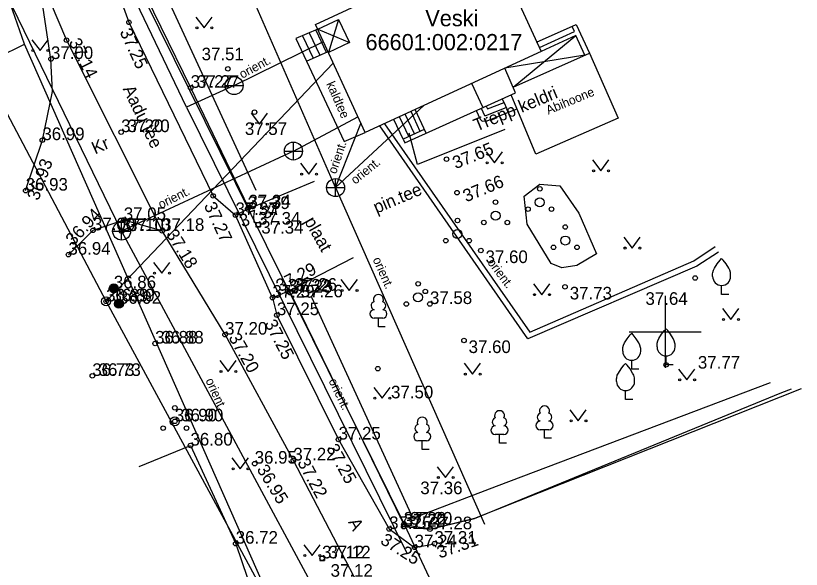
# Model space of a CAD drawing. Extents: x 627548 to 628052, y 6467984 to 6468802.
# Drawn here: x 627663.96 to 627707.55, y 6468336.82 to 6468367.55 of the extents above; entities that cross this region are included whole.
import ezdxf

# ---------------------------------------------------------------- set-up
doc = ezdxf.new("R2010")
doc.units = 0
for name, color, linetype in [('ABIJOONIS', 7, 'Continuous'), ('AED', 7, 'Continuous'), ('HALJASTUS', 7, 'Continuous'), ('HOONE', 7, 'Continuous'), ('HOONEDET', 7, 'Continuous'), ('KKAEV', 7, 'Continuous'), ('KORGUS-EH2000', 7, 'Continuous'), ('KTRASS', 7, 'Continuous'), ('MOOTKORG-EH2000', 7, 'Continuous'), ('MOOTMPUNKT', 7, 'Continuous'), ('MPOHULIIN', 7, 'Continuous'), ('PIIR', 7, 'Continuous'), ('POST', 7, 'Continuous'), ('PUU', 7, 'Continuous'), ('RAJATIS', 7, 'Continuous'), ('SIOHULIIN', 7, 'Continuous'), ('SKKAEV', 7, 'Continuous'), ('SKTRASS', 7, 'Continuous'), ('TEE', 7, 'Continuous'), ('TTRASS', 7, 'Continuous'), ('VKAEV', 7, 'Continuous'), ('VORK', 7, 'Continuous'), ('VTRASS', 7, 'Continuous')]:
    doc.layers.add(name, color=color, linetype=linetype)

msp = doc.modelspace()

# ---------------------------------------------------------------- linework, layer by layer
at = {"layer": 'ABIJOONIS'}
msp.add_lwpolyline([(627691.095, 6468361.243), (627686.259, 6468359.289), (627685.788, 6468361.021)], dxfattribs=at)
at = {"layer": 'AED'}
for p, q in [((627677.288, 6468356.078), (627677.288, 6468355.828)), ((627677.288, 6468356.078), (627677.538, 6468356.078)), ((627677.538, 6468356.078), (627677.538, 6468355.828)), ((627677.288, 6468355.828), (627677.538, 6468355.828)), ((627679.187, 6468352.178), (627685.495, 6468339.298)), ((627679.318, 6468352.408), (627679.318, 6468352.158)), ((627679.318, 6468352.408), (627679.568, 6468352.408)), ((627679.318, 6468352.158), (627679.568, 6468352.158)), ((627679.568, 6468352.408), (627679.568, 6468352.158)), ((627680.837, 6468337.547), (627680.837, 6468337.297)), ((627680.837, 6468337.547), (627681.087, 6468337.547)), ((627680.837, 6468337.297), (627681.087, 6468337.297)), ((627681.087, 6468337.547), (627681.087, 6468337.297))]:
    msp.add_line(p, q, dxfattribs=at)
for points in [[(627676.876, 6468356.909), (627673.668, 6468363.549), (627670.384, 6468370.298)], [(627685.489, 6468339.183), (627686.945, 6468339.039), (627689.41, 6468339.63), (627706.473, 6468346.623), (627707.003, 6468346.838)], [(627670.805, 6468342.532), (627673.658, 6468343.687), (627676.168, 6468338.238), (627677.141, 6468335.391)]]:
    msp.add_lwpolyline(points, dxfattribs=at)
at = {"layer": 'HALJASTUS'}
for p, q in [((627673.956, 6468367.48), (627674.419, 6468366.873)), ((627674.419, 6468366.873), (627674.865, 6468367.48)), ((627664.852, 6468366.221), (627665.316, 6468365.614)), ((627665.316, 6468365.614), (627665.761, 6468366.221)), ((627677.031, 6468362.139), (627677.495, 6468361.532)), ((627677.495, 6468361.532), (627677.94, 6468362.139)), ((627690.061, 6468359.994), (627690.525, 6468359.387)), ((627690.525, 6468359.387), (627690.97, 6468359.994)), ((627695.969, 6468359.549), (627696.432, 6468358.942)), ((627696.432, 6468358.942), (627696.878, 6468359.549)), ((627679.764, 6468359.357), (627680.228, 6468358.75)), ((627680.228, 6468358.75), (627680.673, 6468359.357)), ((627697.709, 6468355.259), (627698.172, 6468354.653)), ((627698.172, 6468354.653), (627698.618, 6468355.259)), ((627671.6, 6468353.857), (627672.064, 6468353.25)), ((627672.064, 6468353.25), (627672.509, 6468353.857)), ((627682.008, 6468352.906), (627682.471, 6468352.299)), ((627682.471, 6468352.299), (627682.917, 6468352.906)), ((627692.691, 6468352.67), (627693.155, 6468352.063)), ((627693.155, 6468352.063), (627693.6, 6468352.67)), ((627703.172, 6468351.294), (627703.635, 6468350.687)), ((627703.635, 6468350.687), (627704.081, 6468351.294)), ((627675.288, 6468348.409), (627675.752, 6468347.802)), ((627675.752, 6468347.802), (627676.197, 6468348.409)), ((627688.847, 6468348.259), (627689.311, 6468347.652)), ((627689.311, 6468347.652), (627689.756, 6468348.259)), ((627700.744, 6468347.935), (627701.207, 6468347.329)), ((627701.207, 6468347.329), (627701.653, 6468347.935)), ((627683.829, 6468346.917), (627684.292, 6468346.31)), ((627684.292, 6468346.31), (627684.738, 6468346.917)), ((627694.715, 6468345.669), (627695.178, 6468345.062)), ((627695.178, 6468345.062), (627695.624, 6468345.669)), ((627675.959, 6468343.002), (627676.422, 6468342.395)), ((627676.422, 6468342.395), (627676.868, 6468343.002)), ((627687.35, 6468342.513), (627687.813, 6468341.906)), ((627687.813, 6468341.906), (627688.259, 6468342.513)), ((627679.941, 6468338.182), (627680.404, 6468337.575)), ((627680.404, 6468337.575), (627680.85, 6468338.182))]:
    msp.add_line(p, q, dxfattribs=at)
for points in [[(627677.3, 6468357.854), (627671.313, 6468370.862)], [(627680.378, 6468351.925), (627685.999, 6468339.649), (627690.64, 6468341.424), (627705.838, 6468347.182)]]:
    msp.add_lwpolyline(points, dxfattribs=at)
msp.add_lwpolyline([(627692.168, 6468357.525), (627693.041, 6468358.202), (627694.161, 6468358.107), (627695.212, 6468356.587), (627696.187, 6468354.33), (627695.094, 6468353.691), (627694.27, 6468353.556), (627693.664, 6468353.792), (627692.336, 6468355.978)], close=True, dxfattribs=at)
for centre, radius in [((627674.018, 6468366.873), 0.055), ((627674.847, 6468366.873), 0.055), ((627664.915, 6468365.614), 0.055), ((627665.744, 6468365.614), 0.055), ((627677.094, 6468361.532), 0.055), ((627677.922, 6468361.532), 0.055), ((627690.123, 6468359.387), 0.055), ((627690.952, 6468359.387), 0.055), ((627696.031, 6468358.942), 0.055), ((627696.86, 6468358.942), 0.055), ((627679.827, 6468358.75), 0.055), ((627680.656, 6468358.75), 0.055), ((627693.042, 6468357.939), 0.125), ((627690.587, 6468357.199), 0.125), ((627693.042, 6468357.189), 0.25), ((627692.392, 6468356.814), 0.125), ((627693.692, 6468356.814), 0.125), ((627690.587, 6468356.449), 0.25), ((627688.474, 6468356.183), 0.125), ((627689.937, 6468356.074), 0.125), ((627691.237, 6468356.074), 0.125), ((627694.455, 6468355.82), 0.125), ((627688.474, 6468355.433), 0.25), ((627687.824, 6468355.058), 0.125), ((627689.124, 6468355.058), 0.125), ((627694.455, 6468355.07), 0.25), ((627693.805, 6468354.695), 0.125), ((627695.105, 6468354.695), 0.125), ((627697.771, 6468354.653), 0.055), ((627698.6, 6468354.653), 0.055), ((627671.663, 6468353.25), 0.055), ((627672.491, 6468353.25), 0.055), ((627686.288, 6468352.668), 0.125), ((627682.07, 6468352.299), 0.055), ((627682.899, 6468352.299), 0.055), ((627686.288, 6468351.918), 0.25), ((627692.754, 6468352.063), 0.055), ((627693.583, 6468352.063), 0.055), ((627685.638, 6468351.543), 0.125), ((627686.938, 6468351.543), 0.125), ((627703.234, 6468350.687), 0.055), ((627704.063, 6468350.687), 0.055), ((627675.351, 6468347.802), 0.055), ((627676.18, 6468347.802), 0.055), ((627688.91, 6468347.652), 0.055), ((627689.738, 6468347.652), 0.055), ((627700.806, 6468347.329), 0.055), ((627701.635, 6468347.329), 0.055), ((627683.891, 6468346.31), 0.055), ((627684.72, 6468346.31), 0.055), ((627694.777, 6468345.062), 0.055), ((627695.606, 6468345.062), 0.055), ((627676.021, 6468342.395), 0.055), ((627676.85, 6468342.395), 0.055), ((627687.412, 6468341.906), 0.055), ((627688.241, 6468341.906), 0.055), ((627680.003, 6468337.575), 0.055), ((627680.832, 6468337.575), 0.055)]:
    msp.add_circle(centre, radius, dxfattribs=at)
at = {"layer": 'HOONE'}
for points in [[(627683.344, 6468361.058), (627680.604, 6468367.07), (627683.347, 6468368.337), (627681.543, 6468372.245), (627686.517, 6468374.421), (627686.768, 6468373.881), (627688.585, 6468374.705), (627688.345, 6468375.224), (627688.627, 6468375.344), (627693.124, 6468365.572), (627683.344, 6468361.058)], [(627680.724, 6468366.805), (627681.873, 6468367.335), (627682.475, 6468366.069), (627681.312, 6468365.516)], [(627695.541, 6468365.357), (627695.045, 6468366.447), (627693.124, 6468365.572)], [(627691.564, 6468363.583), (627695.794, 6468365.47), (627697.389, 6468361.86), (627692.828, 6468359.858), (627691.451, 6468363.164)]]:
    msp.add_lwpolyline(points, dxfattribs=at)
at = {"layer": 'HOONEDET'}
for points in [[(627681.873, 6468367.335), (627681.312, 6468365.516)], [(627692.858, 6468366.087), (627695.061, 6468367.064), (627695.794, 6468365.47)], [(627694.96, 6468366.668), (627694.83, 6468366.961)], [(627680.723, 6468366.809), (627679.504, 6468366.28), (627680.103, 6468365.025), (627681.289, 6468365.566)], [(627679.871, 6468366.439), (627680.467, 6468365.191)], [(627680.238, 6468366.599), (627680.831, 6468365.357)], [(627680.605, 6468366.758), (627681.195, 6468365.523)], [(627680.724, 6468366.805), (627682.475, 6468366.069)], [(627691.564, 6468363.583), (627695.045, 6468366.447)], [(627693.018, 6468365.793), (627694.96, 6468366.668)], [(627695.541, 6468365.357), (627691.094, 6468364.635)], [(627680.103, 6468365.025), (627682.185, 6468360.576), (627683.344, 6468361.058)], [(627686.633, 6468361.234), (627685.453, 6468360.695), (627685.546, 6468360.487), (627691.7, 6468363.277), (627691.094, 6468364.635)], [(627689.885, 6468362.466), (627689.272, 6468363.794)], [(627690.961, 6468362.942), (627691.305, 6468362.188)], [(627690.063, 6468362.535), (627690.135, 6468362.376), (627691.056, 6468362.735)], [(627686.09, 6468360.986), (627685.58, 6468362.09)], [(627686.408, 6468361.131), (627685.898, 6468362.237)], [(627686.731, 6468361.022), (627686.122, 6468362.34)], [(627689.517, 6468362.287), (627689.731, 6468361.814), (627689.837, 6468361.688), (627690.114, 6468361.724), (627691.305, 6468362.188)], [(627689.79, 6468362.411), (627689.972, 6468362.008), (627690.039, 6468362.017), (627691.181, 6468362.461)], [(627691.305, 6468362.188), (627691.78, 6468362.373)], [(627685.453, 6468360.695), (627684.944, 6468361.797)], [(627685.771, 6468360.84), (627685.262, 6468361.943)]]:
    msp.add_lwpolyline(points, dxfattribs=at)
at = {"layer": 'KKAEV'}
for p, q in [((627679.37, 6468359.539), (627679.37, 6468360.539)), ((627678.87, 6468360.039), (627679.87, 6468360.039)), ((627669.837, 6468355.094), (627669.837, 6468356.094)), ((627669.337, 6468355.594), (627670.337, 6468355.594))]:
    msp.add_line(p, q, dxfattribs=at)
for centre in [(627679.37, 6468360.039), (627669.837, 6468355.594)]:
    msp.add_circle(centre, 0.5, dxfattribs=at)
at = {"layer": 'KORGUS-EH2000'}
for centre in [(627670.241, 6468367.186), (627666.781, 6468366.19), (627675.734, 6468364.598), (627677.209, 6468362.197), (627687.869, 6468359.582), (627674.912, 6468357.546), (627688.444, 6468357.728), (627689.773, 6468354.518), (627701.666, 6468352.987), (627694.444, 6468352.498), (627686.687, 6468352.244), (627688.832, 6468349.522), (627684.055, 6468347.956), (627700.051, 6468348.164), (627685.999, 6468339.649)]:
    msp.add_circle(centre, 0.125, dxfattribs=at)
at = {"layer": 'KTRASS'}
for points in [[(627669.837, 6468355.594), (627653.907, 6468388.368), (627661.842, 6468392.243)], [(627679.37, 6468360.039), (627682.943, 6468361.938)], [(627679.37, 6468360.039), (627669.837, 6468355.594)], [(627669.837, 6468355.594), (627687.419, 6468322.91)]]:
    msp.add_lwpolyline(points, dxfattribs=at)
at = {"layer": 'MOOTMPUNKT'}
for centre in [(627665.915, 6468365.146), (627673.668, 6468363.549), (627669.809, 6468361.089), (627665.439, 6468360.645), (627664.511, 6468357.839), (627676.827, 6468356.817), (627676.876, 6468356.909), (627676.157, 6468356.482), (627669.957, 6468356.207), (627677.413, 6468355.953), (627668.244, 6468355.634), (627669.837, 6468355.594), (627672.084, 6468355.605), (627666.883, 6468354.283), (627669.403, 6468352.411), (627678.206, 6468351.895), (627679.054, 6468352.235), (627679.187, 6468352.178), (627679.443, 6468352.283), (627668.977, 6468351.69), (627669.684, 6468351.558), (627678.454, 6468350.927), (627675.577, 6468349.845), (627671.697, 6468349.35), (627668.209, 6468347.553), (627672.788, 6468345.029), (627673.658, 6468343.687), (627681.876, 6468344.022), (627679.367, 6468342.859), (627677.218, 6468342.682), (627685.495, 6468339.298), (627684.682, 6468339.053), (627685.489, 6468339.183), (627686.945, 6468339.039), (627676.168, 6468338.238), (627686.094, 6468338.034), (627687.197, 6468338.236), (627680.962, 6468337.422)]:
    msp.add_circle(centre, 0.125, dxfattribs=at)
at = {"layer": 'MPOHULIIN'}
for points in [[(627647.118, 6468393.14), (627668.977, 6468351.69)], [(627668.977, 6468351.69), (627681.581, 6468364.925)], [(627668.977, 6468351.69), (627685.459, 6468321.228)]]:
    msp.add_lwpolyline(points, dxfattribs=at)
at = {"layer": 'PIIR'}
for p, q in [((627664.45, 6468365.98), (627644.75, 6468421.52)), ((627685.55, 6468339.27), (627668.1, 6468374.6)), ((627653.556, 6468360.522), (627664.45, 6468365.98)), ((627693.67, 6468299.87), (627664.45, 6468365.98)), ((627707.553, 6468346.842), (627689.41, 6468339.63)), ((627689.41, 6468339.63), (627687.01, 6468339.05)), ((627702.17, 6468303.93), (627685.55, 6468339.27)), ((627687.01, 6468339.05), (627685.55, 6468339.27))]:
    msp.add_line(p, q, dxfattribs=at)
at = {"layer": 'POST'}
for radius in [0.25, 0.0234]:
    msp.add_circle((627668.977, 6468351.69), radius, dxfattribs=at)
at = {"layer": 'PUU'}
for p, q in [((627703.134, 6468352.074), (627703.134, 6468352.574)), ((627703.534, 6468352.074), (627703.134, 6468352.074)), ((627684.326, 6468350.754), (627683.846, 6468350.754)), ((627684.086, 6468350.279), (627684.086, 6468350.754)), ((627684.466, 6468350.279), (627684.086, 6468350.279)), ((627700.051, 6468348.164), (627700.051, 6468348.664)), ((627698.141, 6468347.92), (627698.141, 6468348.42)), ((627700.451, 6468348.164), (627700.051, 6468348.164)), ((627698.541, 6468347.92), (627698.141, 6468347.92)), ((627697.799, 6468346.24), (627697.799, 6468346.74)), ((627698.199, 6468346.24), (627697.799, 6468346.24)), ((627691.049, 6468344.3), (627690.569, 6468344.3)), ((627690.809, 6468343.825), (627690.809, 6468344.3)), ((627693.545, 6468344.563), (627693.065, 6468344.563)), ((627693.305, 6468344.088), (627693.305, 6468344.563)), ((627686.759, 6468343.943), (627686.279, 6468343.943)), ((627686.519, 6468343.468), (627686.519, 6468343.943)), ((627691.189, 6468343.825), (627690.809, 6468343.825)), ((627693.685, 6468344.088), (627693.305, 6468344.088)), ((627686.899, 6468343.468), (627686.519, 6468343.468))]:
    msp.add_line(p, q, dxfattribs=at)
for points in [[(627702.634, 6468353.074), (627702.634, 6468353.224), (627702.644, 6468353.289), (627702.679, 6468353.419), (627702.739, 6468353.539), (627702.884, 6468353.774), (627703.044, 6468353.979), (627703.134, 6468354.074)], [(627703.634, 6468353.074), (627703.634, 6468353.224), (627703.624, 6468353.289), (627703.589, 6468353.419), (627703.529, 6468353.539), (627703.384, 6468353.774), (627703.224, 6468353.979), (627703.134, 6468354.074)], [(627697.641, 6468348.92), (627697.641, 6468349.07), (627697.651, 6468349.135), (627697.686, 6468349.265), (627697.746, 6468349.385), (627697.891, 6468349.62), (627698.051, 6468349.825), (627698.141, 6468349.92)], [(627698.641, 6468348.92), (627698.641, 6468349.07), (627698.631, 6468349.135), (627698.596, 6468349.265), (627698.536, 6468349.385), (627698.391, 6468349.62), (627698.231, 6468349.825), (627698.141, 6468349.92)], [(627699.551, 6468349.164), (627699.551, 6468349.314), (627699.561, 6468349.379), (627699.596, 6468349.509), (627699.656, 6468349.629), (627699.801, 6468349.864), (627699.961, 6468350.069), (627700.051, 6468350.164)], [(627700.551, 6468349.164), (627700.551, 6468349.314), (627700.541, 6468349.379), (627700.506, 6468349.509), (627700.446, 6468349.629), (627700.301, 6468349.864), (627700.141, 6468350.069), (627700.051, 6468350.164)], [(627697.299, 6468347.24), (627697.299, 6468347.39), (627697.309, 6468347.455), (627697.344, 6468347.585), (627697.404, 6468347.705), (627697.549, 6468347.94), (627697.709, 6468348.145), (627697.799, 6468348.24)], [(627698.299, 6468347.24), (627698.299, 6468347.39), (627698.289, 6468347.455), (627698.254, 6468347.585), (627698.194, 6468347.705), (627698.049, 6468347.94), (627697.889, 6468348.145), (627697.799, 6468348.24)]]:
    msp.add_lwpolyline(points, dxfattribs=at)
for centre, radius in [((627672.788, 6468345.779), 0.125), ((627672.788, 6468345.029), 0.25), ((627672.138, 6468344.654), 0.125), ((627673.438, 6468344.654), 0.125)]:
    msp.add_circle(centre, radius, dxfattribs=at)
for centre, radius, start, end in [((627703.134, 6468353.074), 0.5, 180, 0), ((627684.086, 6468351.799), 0.277, 332.5799, 207.4201), ((627683.916, 6468351.452), 0.233, 109.0217, 253.1415), ((627684.256, 6468351.452), 0.233, 286.8508, 70.9859), ((627683.849, 6468350.991), 0.238, 90.0016, 269.3953), ((627684.323, 6468350.991), 0.238, 270.6047, 89.9984), ((627700.051, 6468349.164), 0.5, 180, 0), ((627698.141, 6468348.92), 0.5, 180, 0), ((627697.799, 6468347.24), 0.5, 180, 0), ((627690.809, 6468345.345), 0.277, 332.5799, 207.4201), ((627693.135, 6468345.261), 0.233, 109.0217, 253.1415), ((627693.305, 6468345.608), 0.277, 332.5799, 207.4201), ((627693.475, 6468345.261), 0.233, 286.8508, 70.9859), ((627686.519, 6468344.988), 0.277, 332.5799, 207.4201), ((627690.639, 6468344.998), 0.233, 109.0217, 253.1415), ((627690.979, 6468344.998), 0.233, 286.8508, 70.9859), ((627693.068, 6468344.8), 0.238, 90.0016, 269.3953), ((627693.542, 6468344.8), 0.238, 270.6047, 89.9984), ((627686.349, 6468344.641), 0.233, 109.0217, 253.1415), ((627686.689, 6468344.641), 0.233, 286.8508, 70.9859), ((627690.572, 6468344.537), 0.238, 90.0016, 269.3953), ((627691.046, 6468344.537), 0.238, 270.6047, 89.9984), ((627686.282, 6468344.18), 0.238, 90.0016, 269.3953), ((627686.756, 6468344.18), 0.238, 270.6047, 89.9984)]:
    msp.add_arc(centre, radius, start, end, dxfattribs=at)
at = {"layer": 'RAJATIS'}
for centre, radius in [((627669.403, 6468352.411), 0.25), ((627669.403, 6468352.411), 0.225), ((627669.403, 6468352.411), 0.2), ((627669.403, 6468352.411), 0.175), ((627669.403, 6468352.411), 0.15), ((627669.403, 6468352.411), 0.125), ((627669.403, 6468352.411), 0.1), ((627669.403, 6468352.411), 0.075), ((627669.403, 6468352.411), 0.05), ((627669.403, 6468352.411), 0.025), ((627669.684, 6468351.558), 0.25), ((627669.684, 6468351.558), 0.225), ((627669.684, 6468351.558), 0.2), ((627669.684, 6468351.558), 0.175), ((627669.684, 6468351.558), 0.15), ((627669.684, 6468351.558), 0.125), ((627669.684, 6468351.558), 0.1), ((627669.684, 6468351.558), 0.075), ((627669.684, 6468351.558), 0.05), ((627669.684, 6468351.558), 0.025)]:
    msp.add_circle(centre, radius, dxfattribs=at)
at = {"layer": 'SIOHULIIN'}
for points in [[(627647.118, 6468393.14), (627668.977, 6468351.69)], [(627668.977, 6468351.69), (627685.459, 6468321.228)]]:
    msp.add_lwpolyline(points, dxfattribs=at)
at = {"layer": 'SKKAEV'}
for p, q in [((627681.712, 6468357.505), (627681.712, 6468358.505)), ((627681.212, 6468358.005), (627682.212, 6468358.005))]:
    msp.add_line(p, q, dxfattribs=at)
msp.add_circle((627681.712, 6468358.005), 0.5, dxfattribs=at)
at = {"layer": 'SKTRASS'}
for points in [[(627681.712, 6468358.005), (627673.151, 6468377.568)], [(627681.712, 6468358.005), (627686.634, 6468362.576)], [(627681.712, 6468358.005), (627683.11, 6468361.572)], [(627681.712, 6468358.005), (627689.966, 6468339.313)]]:
    msp.add_lwpolyline(points, dxfattribs=at)
at = {"layer": 'TEE'}
for points in [[(627664.163, 6468372.339), (627666.781, 6468366.19), (627672.084, 6468355.605)], [(627669.275, 6468369.857), (627670.241, 6468367.186), (627674.912, 6468357.546), (627676.157, 6468356.482)], [(627664.511, 6468357.839), (627665.439, 6468360.645), (627665.995, 6468363.347), (627665.915, 6468365.146), (627665.379, 6468368.721)], [(627682.692, 6468354.105), (627679.054, 6468352.235), (627678.206, 6468351.895), (627676.157, 6468356.482), (627676.827, 6468356.817), (627680.541, 6468358.373)], [(627705.987, 6468287.879), (627701.575, 6468297.521), (627698.392, 6468302.759), (627693.344, 6468314.297), (627684.494, 6468333.036), (627679.367, 6468342.859), (627675.577, 6468349.845), (627672.084, 6468355.605), (627669.957, 6468356.207), (627668.244, 6468355.634), (627666.883, 6468354.283)], [(627678.206, 6468351.895), (627678.454, 6468350.927), (627681.876, 6468344.022), (627684.682, 6468339.053), (627686.094, 6468338.034), (627687.197, 6468338.236)]]:
    msp.add_lwpolyline(points, dxfattribs=at)
at = {"layer": 'TTRASS'}
for points in [[(627702.954, 6468354.418), (627701.766, 6468353.642), (627692.375, 6468349.612), (627684.159, 6468361.434)], [(627684.418, 6468361.554), (627692.482, 6468349.989)], [(627692.482, 6468349.989), (627701.598, 6468353.949), (627702.78, 6468354.733)]]:
    msp.add_lwpolyline(points, dxfattribs=at)
at = {"layer": 'VKAEV'}
msp.add_line((627675.581, 6468363.674), (627676.581, 6468363.674), dxfattribs=at)
msp.add_circle((627676.081, 6468363.674), 0.5, dxfattribs=at)
at = {"layer": 'VORK'}
for p, q in [((627700, 6468352), (627700, 6468348)), ((627698, 6468350), (627702, 6468350))]:
    msp.add_line(p, q, dxfattribs=at)
at = {"layer": 'VTRASS'}
for points in [[(627673.444, 6468362.479), (627667.441, 6468375)], [(627676.081, 6468363.674), (627681.04, 6468366.113)], [(627676.081, 6468363.674), (627673.444, 6468362.479), (627685.681, 6468337.682)]]:
    msp.add_lwpolyline(points, dxfattribs=at)

# ---------------------------------------------------------------- texts
at = {"layer": 'ABIJOONIS'}
msp.add_text('Trepp keldri', height=0.7, rotation=22.6199, dxfattribs=at).set_placement((627689.537, 6468361.112))
at = {"layer": 'HOONE'}
msp.add_text('Abihoone', height=0.5, rotation=22.6199, dxfattribs=at).set_placement((627693.513, 6468362.053))
at = {"layer": 'HOONEDET'}
msp.add_text('kaldtee', height=0.5, rotation=293.8929, dxfattribs=at).set_placement((627681.182, 6468363.77))
at = {"layer": 'KORGUS-EH2000'}
for s, rotation, p in [(' 37.25 ', 294.64, (627669.605, 6468366.894)), (' 37.14 ', 296.1947, (627666.774, 6468366.332)), (' 37.65 ', 21.8076, (627688.129, 6468358.932)), ('36.93', 69.7171, (627665.216, 6468357.25)), (' 37.66 ', 22.7762, (627688.715, 6468357.083)), ('37.37', 19.9771, (627676.529, 6468355.795)), ('36.94', 47.0081, (627667.162, 6468354.745)), (' 37.27 ', 294.8216, (627674.277, 6468357.252)), ('37.18', 301.6035, (627672.278, 6468355.43)), ('37.29', 27.2153, (627678.633, 6468352.195)), ('37.25', 297.2972, (627677.748, 6468350.469)), ('37.20', 299.5038, (627675.75, 6468349.686)), ('37.25', 298.5788, (627681.179, 6468343.549)), ('37.22', 298.289, (627679.568, 6468342.753)), ('36.95', 301.4002, (627677.31, 6468342.37)), ('37.25', 327.6206, (627684.141, 6468338.282)), ('37.31', 18.9768, (627687.478, 6468337.41))]:
    msp.add_text(s, height=0.7, rotation=rotation, dxfattribs=at).set_placement(p)
for s, p in [(' 37.51 ', (627674.014, 6468365.077)), ('37.27', (627674.018, 6468363.549)), ('37.20', (627670.159, 6468361.089)), (' 37.57 ', (627676.416, 6468360.929)), ('37.10', (627670.187, 6468355.594)), ('37.34', (627677.585, 6468355.453)), (' 37.60 ', (627689.773, 6468353.818)), ('37.26', (627679.771, 6468351.916)), (' 37.73 ', (627694.444, 6468351.798)), ('36.89', (627669.327, 6468351.69)), (' 37.58 ', (627686.687, 6468351.544)), (' 37.64 ', (627698.646, 6468351.498)), ('36.88', (627672.047, 6468349.35)), (' 37.60 ', (627688.832, 6468348.822)), (' 37.77 ', (627701.555, 6468347.957)), ('36.73', (627668.559, 6468347.553)), (' 37.50 ', (627684.527, 6468346.306)), ('36.90', (627673.138, 6468345.029)), (' 37.36 ', (627686.15, 6468340.986)), ('37.20', (627685.845, 6468339.298)), ('37.12', (627681.312, 6468337.422))]:
    msp.add_text(s, height=0.7, dxfattribs=at).set_placement(p)
at = {"layer": 'KTRASS'}
for rotation, p in [(26.6891, (627672.017, 6468356.82)), (294.3985, (627674.479, 6468347.302))]:
    msp.add_text('orient.', height=0.5, rotation=rotation, dxfattribs=at).set_placement(p)
at = {"layer": 'MOOTKORG-EH2000'}
for s, p in [('37.00', (627665.915, 6468365.146)), ('37.27', (627673.668, 6468363.549)), ('37.20', (627669.809, 6468361.089)), ('36.99', (627665.439, 6468360.645)), ('36.93', (627664.511, 6468357.839)), ('37.39', (627676.827, 6468356.817)), ('37.34', (627676.876, 6468356.909)), ('37.05', (627669.957, 6468356.207)), ('37.37', (627676.157, 6468356.482)), ('37.34', (627677.413, 6468355.953)), ('37.00', (627668.244, 6468355.634)), ('37.10', (627669.837, 6468355.594)), ('37.18', (627672.084, 6468355.605)), ('36.94', (627666.883, 6468354.283)), ('36.86', (627669.403, 6468352.411)), ('37.32', (627679.054, 6468352.235)), ('37.23', (627679.187, 6468352.178)), ('37.26', (627679.443, 6468352.283)), ('37.29', (627678.206, 6468351.895)), ('36.89', (627668.977, 6468351.69)), ('36.92', (627669.684, 6468351.558)), ('37.25', (627678.454, 6468350.927)), ('37.20', (627675.577, 6468349.845)), ('36.88', (627671.697, 6468349.35)), ('36.73', (627668.209, 6468347.553)), ('36.90', (627672.788, 6468345.029)), ('37.25', (627681.876, 6468344.022)), ('36.80', (627673.658, 6468343.687)), ('36.95', (627677.218, 6468342.682)), ('37.22', (627679.367, 6468342.859)), ('37.22', (627685.489, 6468339.183)), ('37.20', (627685.495, 6468339.298)), ('37.25', (627684.682, 6468339.053)), ('37.28', (627686.945, 6468339.039)), ('36.72', (627676.168, 6468338.238)), ('37.31', (627687.197, 6468338.236)), ('37.24', (627686.094, 6468338.034)), ('37.12', (627680.962, 6468337.422)), ('37.12', (627681.434, 6468336.401))]:
    msp.add_text(s, height=0.7, dxfattribs=at).set_placement(p)
at = {"layer": 'PIIR'}
for s, p in [('Veski', (627686.69, 6468366.966)), ('66601:002:0217', (627683.369, 6468365.635))]:
    msp.add_text(s, height=0.9, dxfattribs=at).set_placement(p)
at = {"layer": 'SKTRASS'}
for rotation, p in [(71.5038, (627681.735, 6468358.731)), (39.2281, (627682.804, 6468358.162)), (293.973, (627683.757, 6468354.021))]:
    msp.add_text('orient.', height=0.5, rotation=rotation, dxfattribs=at).set_placement(p)
at = {"layer": 'TEE'}
for s, rotation, p in [('Aadu tee', 295.6593, (627669.884, 6468363.49)), ('Kr', 24.1022, (627668.363, 6468359.843)), ('pin.tee', 23.0026, (627683.982, 6468356.555)), ('plaat', 299.4537, (627679.952, 6468356.146)), ('A', 297.4991, (627682.392, 6468339.441))]:
    msp.add_text(s, height=0.7, rotation=rotation, dxfattribs=at).set_placement(p)
at = {"layer": 'TTRASS'}
msp.add_text('orient.', height=0.5, rotation=306.9676, dxfattribs=at).set_placement((627690.111, 6468353.846))
at = {"layer": 'VTRASS'}
for rotation, p in [(28.4402, (627676.53, 6468364.045)), (295.6475, (627681.308, 6468347.277))]:
    msp.add_text('orient.', height=0.5, rotation=rotation, dxfattribs=at).set_placement(p)

doc.saveas('drawing.dxf')
